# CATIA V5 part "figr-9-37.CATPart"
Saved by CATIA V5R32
Part number: Part1
Bounding box of the stored display mesh (mm): x 0 to 200, y -70 to 70, z -70 to 70
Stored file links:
  D:\PROJECTS\Project 2022\CATIA V5 6R 2022\Resources\Part Files\c09_catia_v5_6r2022_prt\c09_catia_v5_6r2022_prt\figr-9-37.CATPart
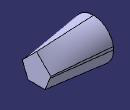
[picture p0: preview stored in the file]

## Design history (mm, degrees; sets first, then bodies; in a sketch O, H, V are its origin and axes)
Set1
  Plane1: type Offset, RefPlane yz-plane, Offset 200
Body1 (main body)
  Sketch1 on yz-plane, origin (0, 0, 0), H (0, 1, 0), V (0, 0, 1)
    circle A1 centre (0, 0) radius 70
    point P1 (70, 0)
    point P2 (-48.9898, -50)
    point P3 (48.9898, -50)
    point P4 (69.282, 10)
    point P5 (-69.282, 10)
    point P6 (0, 70)
    radius A1 = 70
    coincidence: A1 P1, P1 H, P2 A1, P3 A1, P4 A1, P5 A1, P6 V
  Sketch2 on Plane1, origin (200, 0, 0), H (0, 1, 0), V (0, 0, 1)
    point P1 (-30, -40)
    line L1 (-30, -40) -> (30, -40)
    point P2 (30, -40)
    line L2 (30, -40) -> (50, 10)
    point P3 (50, 10)
    line L3 (50, 10) -> (0, 60)
    point P4 (0, 60)
    line L4 (0, 60) -> (-50, 10)
    point P5 (-50, 10)
    line L5 (-50, 10) -> (-30, -40)
    horizontal: L1 H
    coincidence: P4 V
    symmetry: P3 P5 V, P2 P1 V
  Loft1: Sections (edge of Sketch1; Sketch2), SectionCouplingPoints ({coupling CouplingPoints (vertex of Sketch1; vertex [element of Sketch2 | element of Sketch2])}; {coupling CouplingPoints (vertex of Sketch1; vertex [element of Sketch2 | element of Sketch2])}; {coupling CouplingPoints (vertex of Sketch1; vertex [element of Sketch2 | element of Sketch2])}; {coupling CouplingPoints (vertex of Sketch1; vertex [element of Sketch2 | element of Sketch2])})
